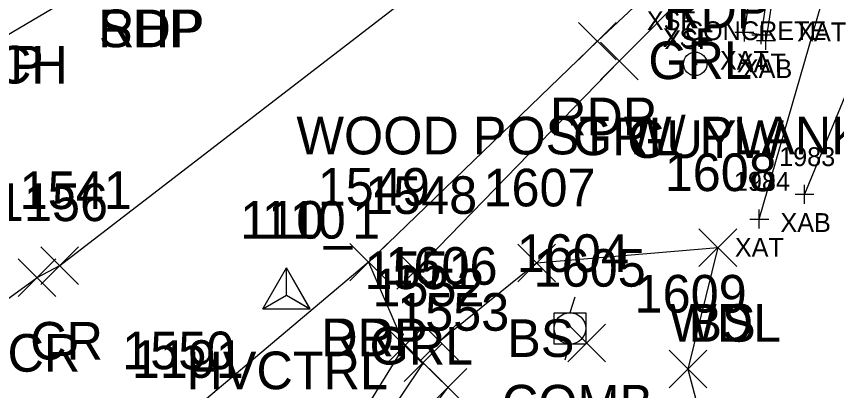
# Model space of a CAD drawing. Extents: x 1647133 to 1649138, y 411736 to 414924.
# Drawn here: x 1648810.32 to 1648853.85, y 412065.88 to 412085.76 of the extents above; entities that cross this region are included whole.
import ezdxf

# ---------------------------------------------------------------- set-up
doc = ezdxf.new("R2010")
doc.units = 0
for name, color, linetype in [('B_A', 7, 'Continuous'), ('B_C', 7, 'Continuous'), ('B_I', 7, 'Continuous'), ('B_TIC', 7, 'Continuous'), ('BSUBM', 7, 'Continuous'), ('C_A', 7, 'Continuous'), ('C_I', 7, 'Continuous'), ('CPSM', 7, 'Continuous'), ('D_A', 7, 'Continuous'), ('D_I', 7, 'Continuous'), ('D_TIC', 7, 'Continuous'), ('DD', 7, 'Continuous'), ('L_A', 7, 'Continuous'), ('L_I', 7, 'Continuous'), ('L_TIC', 7, 'Continuous'), ('LAWA', 7, 'Continuous'), ('LELB', 7, 'Continuous'), ('P_A', 7, 'Continuous'), ('P_I', 7, 'Continuous'), ('P_TIC', 7, 'Continuous'), ('PET', 7, 'Continuous'), ('PRC', 7, 'Continuous'), ('R_A', 7, 'Continuous'), ('R_C', 7, 'Continuous'), ('R_I', 7, 'Continuous'), ('R_TIC', 7, 'Continuous'), ('RDP', 7, 'Continuous'), ('RGR', 7, 'Continuous'), ('U_A', 7, 'Continuous'), ('U_I', 7, 'Continuous'), ('U_TIC', 7, 'Continuous'), ('UP', 7, 'Continuous'), ('UPGW', 7, 'Continuous')]:
    doc.layers.add(name, color=color, linetype=linetype)

msp = doc.modelspace()

# ---------------------------------------------------------------- linework, layer by layer
at = {"layer": 'B_TIC'}
for p, q in [((1648848.96, 412084.934), (1648849.036, 412084.934)), ((1648849.851, 412084.785), (1648849.926, 412084.785)), ((1648850.103, 412084.487), (1648850.178, 412084.487)), ((1648852.152, 412076.311), (1648852.228, 412076.311)), ((1648849.749, 412074.998), (1648849.825, 412074.998))]:
    msp.add_line(p, q, dxfattribs=at)
for points in [[(1648845.86, 412085.63), (1648845.86, 412086.63)], [(1648845.86, 412085.63), (1648845.86, 412086.63)], [(1648845.955, 412085.531), (1648845.955, 412086.531)], [(1648848.957, 412084.434), (1648848.957, 412085.434)], [(1648849.848, 412084.285), (1648849.848, 412085.285)], [(1648848.457, 412084.934), (1648849.457, 412084.934)], [(1648849.348, 412084.785), (1648850.348, 412084.785)], [(1648850.1, 412083.987), (1648850.1, 412084.987)], [(1648849.6, 412084.487), (1648850.6, 412084.487)], [(1648852.149, 412075.811), (1648852.149, 412076.811)], [(1648851.649, 412076.311), (1648852.649, 412076.311)], [(1648849.746, 412074.498), (1648849.746, 412075.498)], [(1648849.246, 412074.998), (1648850.246, 412074.998)]]:
    msp.add_lwpolyline(points, dxfattribs=at)
at = {"layer": 'BSUBM'}
for points in [[(1648834.098, 412112.598), (1648838.135, 412115.208), (1648847.819, 412119.764), (1648865.962, 412097.201), (1648864.743, 412095.384), (1648859.561, 412089.524), (1648855.38, 412084.158), (1648852.149, 412076.311)], [(1648831.501, 412103.876), (1648831.413, 412104.48), (1648835.922, 412104.951), (1648837.246, 412103.531), (1648844.963, 412110.234), (1648856.402, 412097.156), (1648848.705, 412090.291), (1648850.354, 412088.365), (1648849.848, 412084.785), (1648848.957, 412084.934), (1648849.42, 412088.003)], [(1648849.746, 412074.998), (1648853.052, 412086.444), (1648855.254, 412088.323), (1648859.087, 412092.575), (1648859.916, 412094.436), (1648858.907, 412095.188)], [(1648858.907, 412095.188), (1648850.739, 412088.617), (1648850.1, 412084.487)]]:
    msp.add_lwpolyline(points, dxfattribs=at)
at = {"layer": 'CPSM'}
for p, q in [((1648823.401, 412070.235), (1648824.651, 412072.4)), ((1648823.402, 412070.235), (1648824.652, 412072.4)), ((1648823.402, 412070.235), (1648824.652, 412072.4)), ((1648823.402, 412070.235), (1648824.652, 412072.4)), ((1648823.402, 412070.235), (1648824.652, 412072.4)), ((1648825.901, 412070.235), (1648824.651, 412072.4)), ((1648824.652, 412070.956), (1648824.651, 412072.4)), ((1648825.902, 412070.235), (1648824.652, 412072.4)), ((1648824.652, 412070.956), (1648824.652, 412072.4)), ((1648825.902, 412070.235), (1648824.652, 412072.4)), ((1648824.652, 412070.956), (1648824.652, 412072.4)), ((1648825.902, 412070.235), (1648824.652, 412072.4)), ((1648824.652, 412070.956), (1648824.652, 412072.4)), ((1648825.902, 412070.235), (1648824.652, 412072.4)), ((1648824.652, 412070.956), (1648824.652, 412072.4)), ((1648823.401, 412070.235), (1648824.652, 412070.956)), ((1648823.402, 412070.235), (1648824.652, 412070.956)), ((1648823.402, 412070.235), (1648824.652, 412070.956)), ((1648823.402, 412070.235), (1648824.652, 412070.956)), ((1648823.402, 412070.235), (1648824.652, 412070.956)), ((1648824.652, 412070.956), (1648824.652, 412070.956)), ((1648824.652, 412070.956), (1648825.902, 412070.235)), ((1648824.652, 412070.956), (1648824.652, 412070.956)), ((1648824.652, 412070.956), (1648825.902, 412070.235)), ((1648824.652, 412070.956), (1648824.652, 412070.956)), ((1648824.652, 412070.956), (1648825.902, 412070.235)), ((1648824.652, 412070.956), (1648824.652, 412070.956)), ((1648824.652, 412070.956), (1648825.902, 412070.235)), ((1648824.652, 412070.956), (1648824.652, 412070.956)), ((1648824.652, 412070.956), (1648825.901, 412070.235)), ((1648823.401, 412070.235), (1648825.901, 412070.235)), ((1648823.402, 412070.235), (1648825.902, 412070.235)), ((1648823.402, 412070.235), (1648825.902, 412070.235)), ((1648823.402, 412070.235), (1648825.902, 412070.235)), ((1648823.402, 412070.235), (1648825.902, 412070.235))]:
    msp.add_line(p, q, dxfattribs=at)
at = {"layer": 'D_TIC'}
for points in [[(1648829.918, 412067.276), (1648831.918, 412069.276)], [(1648831.918, 412067.276), (1648829.918, 412069.276)], [(1648830.905, 412066.359), (1648832.905, 412068.359)], [(1648832.905, 412066.359), (1648830.905, 412068.359)], [(1648832.22, 412065.063), (1648834.22, 412067.063)], [(1648834.22, 412065.063), (1648832.22, 412067.063)]]:
    msp.add_lwpolyline(points, dxfattribs=at)
at = {"layer": 'DD'}
msp.add_lwpolyline([(1648830.918, 412068.276), (1648831.905, 412067.359), (1648833.22, 412066.063), (1648826.091, 412056.452), (1648811.441, 412039.729)], dxfattribs=at)
at = {"layer": 'L_TIC'}
for points in [[(1648846.547, 412072.481), (1648848.547, 412074.481)], [(1648848.547, 412072.481), (1648846.547, 412074.481)], [(1648846.547, 412072.481), (1648848.547, 412074.481)], [(1648848.547, 412072.481), (1648846.547, 412074.481)], [(1648836.928, 412071.67), (1648838.928, 412073.67)], [(1648838.928, 412071.67), (1648836.928, 412073.67)], [(1648831.78, 412067.505), (1648833.78, 412069.505)], [(1648833.78, 412067.505), (1648831.78, 412069.505)], [(1648830.905, 412066.359), (1648832.905, 412068.359)], [(1648832.905, 412066.359), (1648830.905, 412068.359)], [(1648844.956, 412066.029), (1648846.956, 412068.029)], [(1648846.956, 412066.029), (1648844.956, 412068.029)]]:
    msp.add_lwpolyline(points, dxfattribs=at)
at = {"layer": 'LAWA'}
msp.add_lwpolyline([(1648847.547, 412073.481), (1648845.956, 412067.029), (1648849.396, 412053.935), (1648872.677, 412030.098), (1648893.028, 412013.641), (1648901.106, 412007.99), (1648905.808, 411990.864)], dxfattribs=at)
at = {"layer": 'LELB'}
for points in [[(1648832.78, 412068.505), (1648837.928, 412072.67), (1648847.547, 412073.481)], [(1648831.905, 412067.359), (1648825.15, 412057.266), (1648811.7, 412041.913)]]:
    msp.add_lwpolyline(points, dxfattribs=at)
at = {"layer": 'P_TIC'}
for points in [[(1648840.152, 412083.448), (1648842.152, 412085.448)], [(1648842.152, 412083.448), (1648840.152, 412085.448)], [(1648811.617, 412071.528), (1648813.617, 412073.528)], [(1648813.617, 412071.528), (1648811.617, 412073.528)], [(1648811.617, 412071.528), (1648813.617, 412073.528)], [(1648813.617, 412071.528), (1648811.617, 412073.528)], [(1648828.009, 412071.706), (1648830.009, 412073.706)], [(1648830.009, 412071.706), (1648828.009, 412073.706)], [(1648810.415, 412070.887), (1648812.415, 412072.887)], [(1648812.415, 412070.887), (1648810.415, 412072.887)]]:
    msp.add_lwpolyline(points, dxfattribs=at)
at = {"layer": 'PET'}
msp.add_lwpolyline([(1648804.077, 412081.379), (1648817.165, 412089.126), (1648824.651, 412094.018), (1648832.497, 412099.297), (1648836.674, 412102.355), (1648842.257, 412096.253), (1648847.201, 412090.123), (1648841.152, 412084.448), (1648829.009, 412072.706), (1648818.716, 412064.019)], dxfattribs=at)
at = {"layer": 'PRC'}
for points in [[(1648812.617, 412072.528), (1648836.598, 412091.021), (1648842.257, 412096.253)], [(1648776.375, 412047.027), (1648793.935, 412059.182), (1648811.415, 412071.887), (1648812.617, 412072.528)]]:
    msp.add_lwpolyline(points, dxfattribs=at)
at = {"layer": 'R_TIC'}
for points in [[(1648841.313, 412082.387), (1648843.313, 412084.387)], [(1648843.313, 412082.387), (1648841.313, 412084.387)], [(1648828.009, 412071.706), (1648830.009, 412073.706)], [(1648830.009, 412071.706), (1648828.009, 412073.706)], [(1648830.517, 412071.268), (1648832.517, 412073.268)], [(1648832.517, 412071.268), (1648830.517, 412073.268)], [(1648829.918, 412067.276), (1648831.918, 412069.276)], [(1648831.918, 412067.276), (1648829.918, 412069.276)]]:
    msp.add_lwpolyline(points, dxfattribs=at)
at = {"layer": 'RDP'}
msp.add_lwpolyline([(1648829.009, 412072.706), (1648830.918, 412068.276), (1648824.437, 412057.772), (1648808.952, 412041.997), (1648811.441, 412039.729)], dxfattribs=at)
at = {"layer": 'RGR'}
msp.add_lwpolyline([(1648846.316, 412087.432), (1648842.313, 412083.387), (1648831.517, 412072.268)], dxfattribs=at)
at = {"layer": 'U_TIC'}
for points in [[(1648839.588, 412067.404), (1648841.588, 412069.404)], [(1648841.588, 412067.404), (1648839.588, 412069.404)]]:
    msp.add_lwpolyline(points, dxfattribs=at)
at = {"layer": 'UP'}
for p, q in [((1648839.95, 412070.854), (1648839.7, 412070.021)), ((1648838.867, 412068.354), (1648838.867, 412070.021)), ((1648838.867, 412070.021), (1648840.534, 412070.021)), ((1648840.534, 412070.021), (1648840.534, 412068.354)), ((1648839.7, 412069.188), (1648839.7, 412069.188)), ((1648840.534, 412068.354), (1648838.867, 412068.354)), ((1648839.45, 412067.521), (1648839.7, 412068.354))]:
    msp.add_line(p, q, dxfattribs=at)
msp.add_circle((1648839.7, 412069.188), 0.833, dxfattribs=at)
at = {"layer": 'UPGW'}
for radius in [0.625, 0.0833]:
    msp.add_circle((1648846.347, 412083.243), radius, dxfattribs=at)

# ---------------------------------------------------------------- texts
at = {"layer": 'B_A'}
for s, p in [('XSF', (1648843.778, 412085.036)), ('XAT', (1648851.757, 412084.444)), ('XSF', (1648844.62, 412084.13)), ('XSF', (1648844.62, 412084.13)), ('XSF', (1648844.715, 412084.031)), ('XAT', (1648847.661, 412082.934)), ('XAT', (1648848.552, 412082.785)), ('XAB', (1648848.82, 412082.487)), ('XAB', (1648850.869, 412074.311)), ('XAT', (1648848.451, 412072.998))]:
    msp.add_text(s, height=1, dxfattribs=at).set_placement(p)
at = {"layer": 'B_C'}
msp.add_text('CONCRETE', height=1, dxfattribs=at).set_placement((1648845.798, 412084.503))
msp.add_text('CONCRETE', height=1, dxfattribs=at).set_placement((1648845.798, 412084.503))
at = {"layer": 'B_I'}
for s, p in [('1983', (1648850.802, 412077.811)), ('1984', (1648848.4, 412076.498))]:
    msp.add_text(s, height=1, dxfattribs=at).set_placement(p)
at = {"layer": 'C_A'}
msp.add_text('HVCTRL', height=2, dxfattribs=at).set_placement((1648819.345, 412065.956))
msp.add_text('HVCTRL', height=2, dxfattribs=at).set_placement((1648819.345, 412065.956))
msp.add_text('HVCTRL', height=2, dxfattribs=at).set_placement((1648819.345, 412065.956))
msp.add_text('HVCTRL', height=2, dxfattribs=at).set_placement((1648819.345, 412065.956))
msp.add_text('HVCTRL', height=2, dxfattribs=at).set_placement((1648819.345, 412065.956))
at = {"layer": 'C_I'}
for s, p in [('110_1', (1648822.195, 412073.956)), ('110', (1648823.337, 412073.956)), ('110', (1648823.337, 412073.956)), ('110', (1648823.337, 412073.956)), ('110', (1648823.337, 412073.956))]:
    msp.add_text(s, height=2, dxfattribs=at).set_placement(p)
at = {"layer": 'D_A'}
msp.add_text('DITCH', height=2, dxfattribs=at).set_placement((1648804.873, 412082.198))
at = {"layer": 'D_I'}
for s, p in [('1551', (1648828.792, 412071.276)), ('1552', (1648829.212, 412070.359)), ('1553', (1648830.527, 412069.063))]:
    msp.add_text(s, height=2, dxfattribs=at).set_placement(p)
at = {"layer": 'L_A'}
for s, p in [('WDL', (1648844.964, 412068.481)), ('BS', (1648845.988, 412068.481)), ('BS', (1648836.369, 412067.67))]:
    msp.add_text(s, height=2, dxfattribs=at).set_placement(p)
at = {"layer": 'L_I'}
for s, p in [('1608', (1648844.728, 412076.481)), ('1608', (1648844.728, 412076.481)), ('1607', (1648835.109, 412075.67)), ('1606', (1648829.906, 412071.505)), ('1552', (1648829.212, 412070.359)), ('1609', (1648843.129, 412070.029))]:
    msp.add_text(s, height=2, dxfattribs=at).set_placement(p)
at = {"layer": 'P_A'}
for s, p in [('RDP', (1648844.689, 412085.123)), ('SHP', (1648814.7, 412084.126)), ('RDP', (1648814.653, 412084.126)), ('RDP', (1648838.64, 412079.448)), ('CR', (1648811.05, 412067.528)), ('CR', (1648811.05, 412067.528)), ('RDP', (1648826.498, 412067.706)), ('CR', (1648809.848, 412066.887))]:
    msp.add_text(s, height=2, dxfattribs=at).set_placement(p)
at = {"layer": 'P_I'}
for s, p in [('1541', (1648810.491, 412075.528)), ('1541', (1648810.491, 412075.528)), ('1549', (1648826.309, 412075.706)), ('1156', (1648809.233, 412074.887)), ('1550', (1648815.937, 412067.019)), ('1550', (1648815.937, 412067.019)), ('1191', (1648816.442, 412066.558)), ('1191', (1648816.442, 412066.558))]:
    msp.add_text(s, height=2, dxfattribs=at).set_placement(p)
at = {"layer": 'R_A'}
for s, p in [('GRL', (1648843.859, 412082.432)), ('DRP', (1648806.125, 412082.198)), ('GRL', (1648839.856, 412078.387)), ('DRP', (1648826.498, 412067.706)), ('GRL', (1648829.06, 412067.268))]:
    msp.add_text(s, height=2, dxfattribs=at).set_placement(p)
at = {"layer": 'R_C'}
msp.add_text('WOOD POST W/ PLANK RAIL', height=2, dxfattribs=at).set_placement((1648825.182, 412078.432))
at = {"layer": 'R_I'}
for s, p in [('1549', (1648826.309, 412075.706)), ('1548', (1648828.824, 412075.268)), ('1551', (1648828.792, 412071.276))]:
    msp.add_text(s, height=2, dxfattribs=at).set_placement(p)
at = {"layer": 'U_A'}
for s, p in [('GUYW', (1648842.741, 412078.243)), ('COMB', (1648836.086, 412064.188))]:
    msp.add_text(s, height=2, dxfattribs=at).set_placement(p)
at = {"layer": 'U_I'}
for s, p in [('1604', (1648836.882, 412072.188)), ('1605', (1648837.769, 412071.404))]:
    msp.add_text(s, height=2, dxfattribs=at).set_placement(p)

doc.saveas('drawing.dxf')
